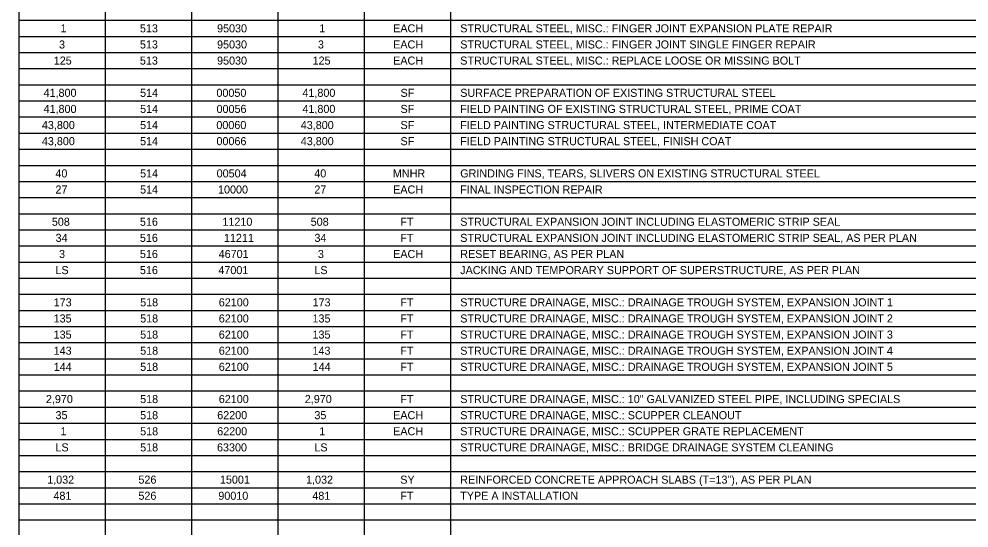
# Model space of a CAD drawing. Extents: x 100 to 128, y 64.8 to 100.
# Drawn here: x 100 to 116.51, y 82.3 to 91.14 of the extents above; entities that cross this region are included whole.
import ezdxf

# ---------------------------------------------------------------- set-up
doc = ezdxf.new("R2010")
doc.units = 0
doc.layers.add('SH_Text', color=7, linetype='Continuous')

msp = doc.modelspace()

# ---------------------------------------------------------------- linework, layer by layer
at = {"layer": 'SH_Text'}
for p, q in [((100, 91.4), (100, 91.12)), ((101.5, 91.4), (101.5, 91.12)), ((103, 91.4), (103, 91.12)), ((104.5, 91.4), (104.5, 91.12)), ((106, 91.4), (106, 91.12)), ((107.5, 91.4), (107.5, 91.12)), ((100, 91.12), (128, 91.12)), ((100, 91.12), (100, 90.84)), ((101.5, 91.12), (101.5, 90.84)), ((103, 91.12), (103, 90.84)), ((104.5, 91.12), (104.5, 90.84)), ((106, 91.12), (106, 90.84)), ((107.5, 91.12), (107.5, 90.84)), ((100, 90.84), (128, 90.84)), ((100, 90.84), (100, 90.56)), ((101.5, 90.84), (101.5, 90.56)), ((103, 90.84), (103, 90.56)), ((104.5, 90.84), (104.5, 90.56)), ((106, 90.84), (106, 90.56)), ((107.5, 90.84), (107.5, 90.56)), ((100, 90.56), (128, 90.56)), ((100, 90.56), (100, 90.28)), ((101.5, 90.56), (101.5, 90.28)), ((103, 90.56), (103, 90.28)), ((104.5, 90.56), (104.5, 90.28)), ((106, 90.56), (106, 90.28)), ((107.5, 90.56), (107.5, 90.28)), ((100, 90.28), (128, 90.28)), ((100, 90.28), (100, 90)), ((101.5, 90.28), (101.5, 90)), ((103, 90.28), (103, 90)), ((104.5, 90.28), (104.5, 90)), ((106, 90.28), (106, 90)), ((107.5, 90.28), (107.5, 90)), ((100, 90), (128, 90)), ((100, 90), (100, 89.72)), ((101.5, 90), (101.5, 89.72)), ((103, 90), (103, 89.72)), ((104.5, 90), (104.5, 89.72)), ((106, 90), (106, 89.72)), ((107.5, 90), (107.5, 89.72)), ((100, 89.72), (128, 89.72)), ((100, 89.72), (100, 89.44)), ((101.5, 89.72), (101.5, 89.44)), ((103, 89.72), (103, 89.44)), ((104.5, 89.72), (104.5, 89.44)), ((106, 89.72), (106, 89.44)), ((107.5, 89.72), (107.5, 89.44)), ((100, 89.44), (128, 89.44)), ((100, 89.44), (100, 89.16)), ((101.5, 89.44), (101.5, 89.16)), ((103, 89.44), (103, 89.16)), ((104.5, 89.44), (104.5, 89.16)), ((106, 89.44), (106, 89.16)), ((107.5, 89.44), (107.5, 89.16)), ((100, 89.16), (128, 89.16)), ((100, 89.16), (100, 88.88)), ((101.5, 89.16), (101.5, 88.88)), ((103, 89.16), (103, 88.88)), ((104.5, 89.16), (104.5, 88.88)), ((106, 89.16), (106, 88.88)), ((107.5, 89.16), (107.5, 88.88)), ((100, 88.88), (128, 88.88)), ((100, 88.88), (100, 88.6)), ((101.5, 88.88), (101.5, 88.6)), ((103, 88.88), (103, 88.6)), ((104.5, 88.88), (104.5, 88.6)), ((106, 88.88), (106, 88.6)), ((107.5, 88.88), (107.5, 88.6)), ((100, 88.6), (128, 88.6)), ((100, 88.6), (100, 88.32)), ((101.5, 88.6), (101.5, 88.32)), ((103, 88.6), (103, 88.32)), ((104.5, 88.6), (104.5, 88.32)), ((106, 88.6), (106, 88.32)), ((107.5, 88.6), (107.5, 88.32)), ((100, 88.32), (128, 88.32)), ((100, 88.32), (100, 88.04)), ((101.5, 88.32), (101.5, 88.04)), ((103, 88.32), (103, 88.04)), ((104.5, 88.32), (104.5, 88.04)), ((106, 88.32), (106, 88.04)), ((107.5, 88.32), (107.5, 88.04)), ((100, 88.04), (128, 88.04)), ((100, 88.04), (100, 87.76)), ((101.5, 88.04), (101.5, 87.76)), ((103, 88.04), (103, 87.76)), ((104.5, 88.04), (104.5, 87.76)), ((106, 88.04), (106, 87.76)), ((107.5, 88.04), (107.5, 87.76)), ((100, 87.76), (128, 87.76)), ((100, 87.76), (100, 87.48)), ((101.5, 87.76), (101.5, 87.48)), ((103, 87.76), (103, 87.48)), ((104.5, 87.76), (104.5, 87.48)), ((106, 87.76), (106, 87.48)), ((107.5, 87.76), (107.5, 87.48)), ((100, 87.48), (128, 87.48)), ((100, 87.48), (100, 87.2)), ((101.5, 87.48), (101.5, 87.2)), ((103, 87.48), (103, 87.2)), ((104.5, 87.48), (104.5, 87.2)), ((106, 87.48), (106, 87.2)), ((107.5, 87.48), (107.5, 87.2)), ((100, 87.2), (128, 87.2)), ((100, 87.2), (100, 86.92)), ((101.5, 87.2), (101.5, 86.92)), ((103, 87.2), (103, 86.92)), ((104.5, 87.2), (104.5, 86.92)), ((106, 87.2), (106, 86.92)), ((107.5, 87.2), (107.5, 86.92)), ((100, 86.92), (128, 86.92)), ((100, 86.92), (100, 86.64)), ((101.5, 86.92), (101.5, 86.64)), ((103, 86.92), (103, 86.64)), ((104.5, 86.92), (104.5, 86.64)), ((106, 86.92), (106, 86.64)), ((107.5, 86.92), (107.5, 86.64)), ((100, 86.64), (128, 86.64)), ((100, 86.64), (100, 86.36)), ((101.5, 86.64), (101.5, 86.36)), ((103, 86.64), (103, 86.36)), ((104.5, 86.64), (104.5, 86.36)), ((106, 86.64), (106, 86.36)), ((107.5, 86.64), (107.5, 86.36)), ((100, 86.36), (128, 86.36)), ((100, 86.36), (100, 86.08)), ((101.5, 86.36), (101.5, 86.08)), ((103, 86.36), (103, 86.08)), ((104.5, 86.36), (104.5, 86.08)), ((106, 86.36), (106, 86.08)), ((107.5, 86.36), (107.5, 86.08)), ((100, 86.08), (128, 86.08)), ((100, 86.08), (100, 85.8)), ((101.5, 86.08), (101.5, 85.8)), ((103, 86.08), (103, 85.8)), ((104.5, 86.08), (104.5, 85.8)), ((106, 86.08), (106, 85.8)), ((107.5, 86.08), (107.5, 85.8)), ((100, 85.8), (128, 85.8)), ((100, 85.8), (100, 85.52)), ((101.5, 85.8), (101.5, 85.52)), ((103, 85.8), (103, 85.52)), ((104.5, 85.8), (104.5, 85.52)), ((106, 85.8), (106, 85.52)), ((107.5, 85.8), (107.5, 85.52)), ((100, 85.52), (128, 85.52)), ((100, 85.52), (100, 85.24)), ((101.5, 85.52), (101.5, 85.24)), ((103, 85.52), (103, 85.24)), ((104.5, 85.52), (104.5, 85.24)), ((106, 85.52), (106, 85.24)), ((107.5, 85.52), (107.5, 85.24)), ((100, 85.24), (128, 85.24)), ((100, 85.24), (100, 84.96)), ((101.5, 85.24), (101.5, 84.96)), ((103, 85.24), (103, 84.96)), ((104.5, 85.24), (104.5, 84.96)), ((106, 85.24), (106, 84.96)), ((107.5, 85.24), (107.5, 84.96)), ((100, 84.96), (128, 84.96)), ((100, 84.96), (100, 84.68)), ((101.5, 84.96), (101.5, 84.68)), ((103, 84.96), (103, 84.68)), ((104.5, 84.96), (104.5, 84.68)), ((106, 84.96), (106, 84.68)), ((107.5, 84.96), (107.5, 84.68)), ((100, 84.68), (128, 84.68)), ((100, 84.68), (100, 84.4)), ((101.5, 84.68), (101.5, 84.4)), ((103, 84.68), (103, 84.4)), ((104.5, 84.68), (104.5, 84.4)), ((106, 84.68), (106, 84.4)), ((107.5, 84.68), (107.5, 84.4)), ((100, 84.4), (128, 84.4)), ((100, 84.4), (100, 84.12)), ((101.5, 84.4), (101.5, 84.12)), ((103, 84.4), (103, 84.12)), ((104.5, 84.4), (104.5, 84.12)), ((106, 84.4), (106, 84.12)), ((107.5, 84.4), (107.5, 84.12)), ((100, 84.12), (128, 84.12)), ((100, 84.12), (100, 83.84)), ((101.5, 84.12), (101.5, 83.84)), ((103, 84.12), (103, 83.84)), ((104.5, 84.12), (104.5, 83.84)), ((106, 84.12), (106, 83.84)), ((107.5, 84.12), (107.5, 83.84)), ((100, 83.84), (128, 83.84)), ((100, 83.84), (100, 83.56)), ((101.5, 83.84), (101.5, 83.56)), ((103, 83.84), (103, 83.56)), ((104.5, 83.84), (104.5, 83.56)), ((106, 83.84), (106, 83.56)), ((107.5, 83.84), (107.5, 83.56)), ((100, 83.56), (128, 83.56)), ((100, 83.56), (100, 83.28)), ((101.5, 83.56), (101.5, 83.28)), ((103, 83.56), (103, 83.28)), ((104.5, 83.56), (104.5, 83.28)), ((106, 83.56), (106, 83.28)), ((107.5, 83.56), (107.5, 83.28)), ((100, 83.28), (128, 83.28)), ((100, 83.28), (100, 83)), ((101.5, 83.28), (101.5, 83)), ((103, 83.28), (103, 83)), ((104.5, 83.28), (104.5, 83)), ((106, 83.28), (106, 83)), ((107.5, 83.28), (107.5, 83)), ((100, 83), (128, 83)), ((100, 83), (100, 82.72)), ((101.5, 83), (101.5, 82.72)), ((103, 83), (103, 82.72)), ((104.5, 83), (104.5, 82.72)), ((106, 83), (106, 82.72)), ((107.5, 83), (107.5, 82.72)), ((100, 82.72), (128, 82.72)), ((100, 82.72), (100, 82.44)), ((101.5, 82.72), (101.5, 82.44)), ((103, 82.72), (103, 82.44)), ((104.5, 82.72), (104.5, 82.44)), ((106, 82.72), (106, 82.44)), ((107.5, 82.72), (107.5, 82.44)), ((100, 82.44), (128, 82.44)), ((100, 82.44), (100, 82.16)), ((101.5, 82.44), (101.5, 82.16)), ((103, 82.44), (103, 82.16)), ((104.5, 82.44), (104.5, 82.16)), ((106, 82.44), (106, 82.16)), ((107.5, 82.44), (107.5, 82.16))]:
    msp.add_line(p, q, dxfattribs=at)

# ---------------------------------------------------------------- texts
for s, p in [('1', (100.721, 90.91)), ('513', (102.102, 90.91)), ('95030', (103.443, 90.91)), ('1', (105.221, 90.91)), ('EACH', (106.504, 90.91)), ('STRUCTURAL STEEL, MISC.: FINGER JOINT EXPANSION PLATE REPAIR', (107.67, 90.91)), ('3', (100.696, 90.63)), ('513', (102.102, 90.63)), ('95030', (103.443, 90.63)), ('3', (105.196, 90.63)), ('EACH', (106.504, 90.63)), ('STRUCTURAL STEEL, MISC.: FINGER JOINT SINGLE FINGER REPAIR', (107.67, 90.63)), ('125', (100.604, 90.35)), ('513', (102.102, 90.35)), ('95030', (103.443, 90.35)), ('125', (105.104, 90.35)), ('EACH', (106.504, 90.35)), ('STRUCTURAL STEEL, MISC.: REPLACE LOOSE OR MISSING BOLT', (107.67, 90.35)), ('41,800', (100.427, 89.79)), ('514', (102.105, 89.79)), ('00050', (103.432, 89.79)), ('41,800', (104.927, 89.79)), ('SF', (106.632, 89.79)), ('SURFACE PREPARATION OF EXISTING STRUCTURAL STEEL', (107.67, 89.79)), ('41,800', (100.427, 89.51)), ('514', (102.105, 89.51)), ('00056', (103.434, 89.51)), ('41,800', (104.927, 89.51)), ('SF', (106.632, 89.51)), ('FIELD PAINTING OF EXISTING STRUCTURAL STEEL, PRIME COAT', (107.67, 89.51)), ('43,800', (100.398, 89.23)), ('514', (102.105, 89.23)), ('00060', (103.431, 89.23)), ('43,800', (104.898, 89.23)), ('SF', (106.632, 89.23)), ('FIELD PAINTING STRUCTURAL STEEL, INTERMEDIATE COAT', (107.67, 89.23)), ('43,800', (100.398, 88.95)), ('514', (102.105, 88.95)), ('00066', (103.433, 88.95)), ('43,800', (104.898, 88.95)), ('SF', (106.632, 88.95)), ('FIELD PAINTING STRUCTURAL STEEL, FINISH COAT', (107.67, 88.95)), ('40', (100.633, 88.39)), ('514', (102.105, 88.39)), ('00504', (103.436, 88.39)), ('40', (105.133, 88.39)), ('MNHR', (106.499, 88.39)), ('GRINDING FINS, TEARS, SLIVERS ON EXISTING STRUCTURAL STEEL', (107.67, 88.39)), ('27', (100.634, 88.11)), ('514', (102.105, 88.11)), ('10000', (103.46, 88.11)), ('27', (105.134, 88.11)), ('EACH', (106.504, 88.11)), ('FINAL INSPECTION REPAIR', (107.67, 88.11)), ('508', (100.571, 87.55)), ('516', (102.102, 87.55)), ('11210', (103.536, 87.55)), ('508', (105.071, 87.55)), ('STRUCTURAL EXPANSION JOINT INCLUDING ELASTOMERIC STRIP SEAL', (107.67, 87.55)), ('FT', (106.628, 87.55)), ('34', (100.636, 87.27)), ('516', (102.102, 87.27)), ('11211', (103.562, 87.27)), ('34', (105.136, 87.27)), ('FT', (106.628, 87.27)), ('STRUCTURAL EXPANSION JOINT INCLUDING ELASTOMERIC STRIP SEAL, AS PER PLAN', (107.67, 87.27)), ('3', (100.696, 86.99)), ('516', (102.102, 86.99)), ('46701', (103.471, 86.99)), ('3', (105.196, 86.99)), ('EACH', (106.504, 86.99)), ('RESET BEARING, AS PER PLAN', (107.67, 86.99)), ('LS', (100.634, 86.71)), ('516', (102.102, 86.71)), ('47001', (103.466, 86.71)), ('LS', (105.134, 86.71)), ('JACKING AND TEMPORARY SUPPORT OF SUPERSTRUCTURE, AS PER PLAN', (107.67, 86.71)), ('173', (100.603, 86.15)), ('518', (102.106, 86.15)), ('62100', (103.473, 86.15)), ('173', (105.103, 86.15)), ('FT', (106.628, 86.15)), ('STRUCTURE DRAINAGE, MISC.: DRAINAGE TROUGH SYSTEM, EXPANSION JOINT 1', (107.67, 86.15)), ('135', (100.602, 85.87)), ('518', (102.106, 85.87)), ('62100', (103.473, 85.87)), ('135', (105.102, 85.87)), ('FT', (106.628, 85.87)), ('STRUCTURE DRAINAGE, MISC.: DRAINAGE TROUGH SYSTEM, EXPANSION JOINT 2', (107.67, 85.87)), ('135', (100.602, 85.59)), ('518', (102.106, 85.59)), ('62100', (103.473, 85.59)), ('135', (105.102, 85.59)), ('FT', (106.628, 85.59)), ('STRUCTURE DRAINAGE, MISC.: DRAINAGE TROUGH SYSTEM, EXPANSION JOINT 3', (107.67, 85.59)), ('143', (100.602, 85.31)), ('518', (102.106, 85.31)), ('62100', (103.473, 85.31)), ('143', (105.102, 85.31)), ('FT', (106.628, 85.31)), ('STRUCTURE DRAINAGE, MISC.: DRAINAGE TROUGH SYSTEM, EXPANSION JOINT 4', (107.67, 85.31)), ('144', (100.604, 85.03)), ('518', (102.106, 85.03)), ('62100', (103.473, 85.03)), ('144', (105.104, 85.03)), ('FT', (106.628, 85.03)), ('STRUCTURE DRAINAGE, MISC.: DRAINAGE TROUGH SYSTEM, EXPANSION JOINT 5', (107.67, 85.03)), ('2,970', (100.468, 84.47)), ('518', (102.106, 84.47)), ('62100', (103.473, 84.47)), ('2,970', (104.968, 84.47)), ('FT', (106.628, 84.47)), ('STRUCTURE DRAINAGE, MISC.: 10" GALVANIZED STEEL PIPE, INCLUDING SPECIALS', (107.67, 84.47)), ('35', (100.635, 84.19)), ('518', (102.106, 84.19)), ('62200', (103.446, 84.19)), ('35', (105.135, 84.19)), ('EACH', (106.504, 84.19)), ('STRUCTURE DRAINAGE, MISC.: SCUPPER CLEANOUT', (107.67, 84.19)), ('1', (100.721, 83.91)), ('518', (102.106, 83.91)), ('62200', (103.446, 83.91)), ('1', (105.221, 83.91)), ('EACH', (106.504, 83.91)), ('STRUCTURE DRAINAGE, MISC.: SCUPPER GRATE REPLACEMENT', (107.67, 83.91)), ('LS', (100.634, 83.63)), ('518', (102.106, 83.63)), ('63300', (103.442, 83.63)), ('LS', (105.134, 83.63)), ('STRUCTURE DRAINAGE, MISC.: BRIDGE DRAINAGE SYSTEM CLEANING', (107.67, 83.63)), ('1,032', (100.49, 83.07)), ('526', (102.076, 83.07)), ('15001', (103.493, 83.07)), ('1,032', (104.99, 83.07)), ('SY', (106.628, 83.07)), ('REINFORCED CONCRETE APPROACH SLABS (T=13"), AS PER PLAN', (107.67, 83.07)), ('481', (100.599, 82.79)), ('526', (102.076, 82.79)), ('90010', (103.465, 82.79)), ('481', (105.099, 82.79)), ('FT', (106.628, 82.79)), ('TYPE A INSTALLATION', (107.67, 82.79))]:
    msp.add_text(s, height=0.14, dxfattribs=at).set_placement(p)

doc.saveas('drawing.dxf')
